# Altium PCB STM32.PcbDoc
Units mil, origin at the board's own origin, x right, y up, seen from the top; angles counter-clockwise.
Board outline 4734.45 x 4734.65 mil, 2 copper layers (Top Layer, Bottom Layer); 1 components, 161 nets, 42 pads, 0 vias.
Unrouted connection lines stored in the file: 460.
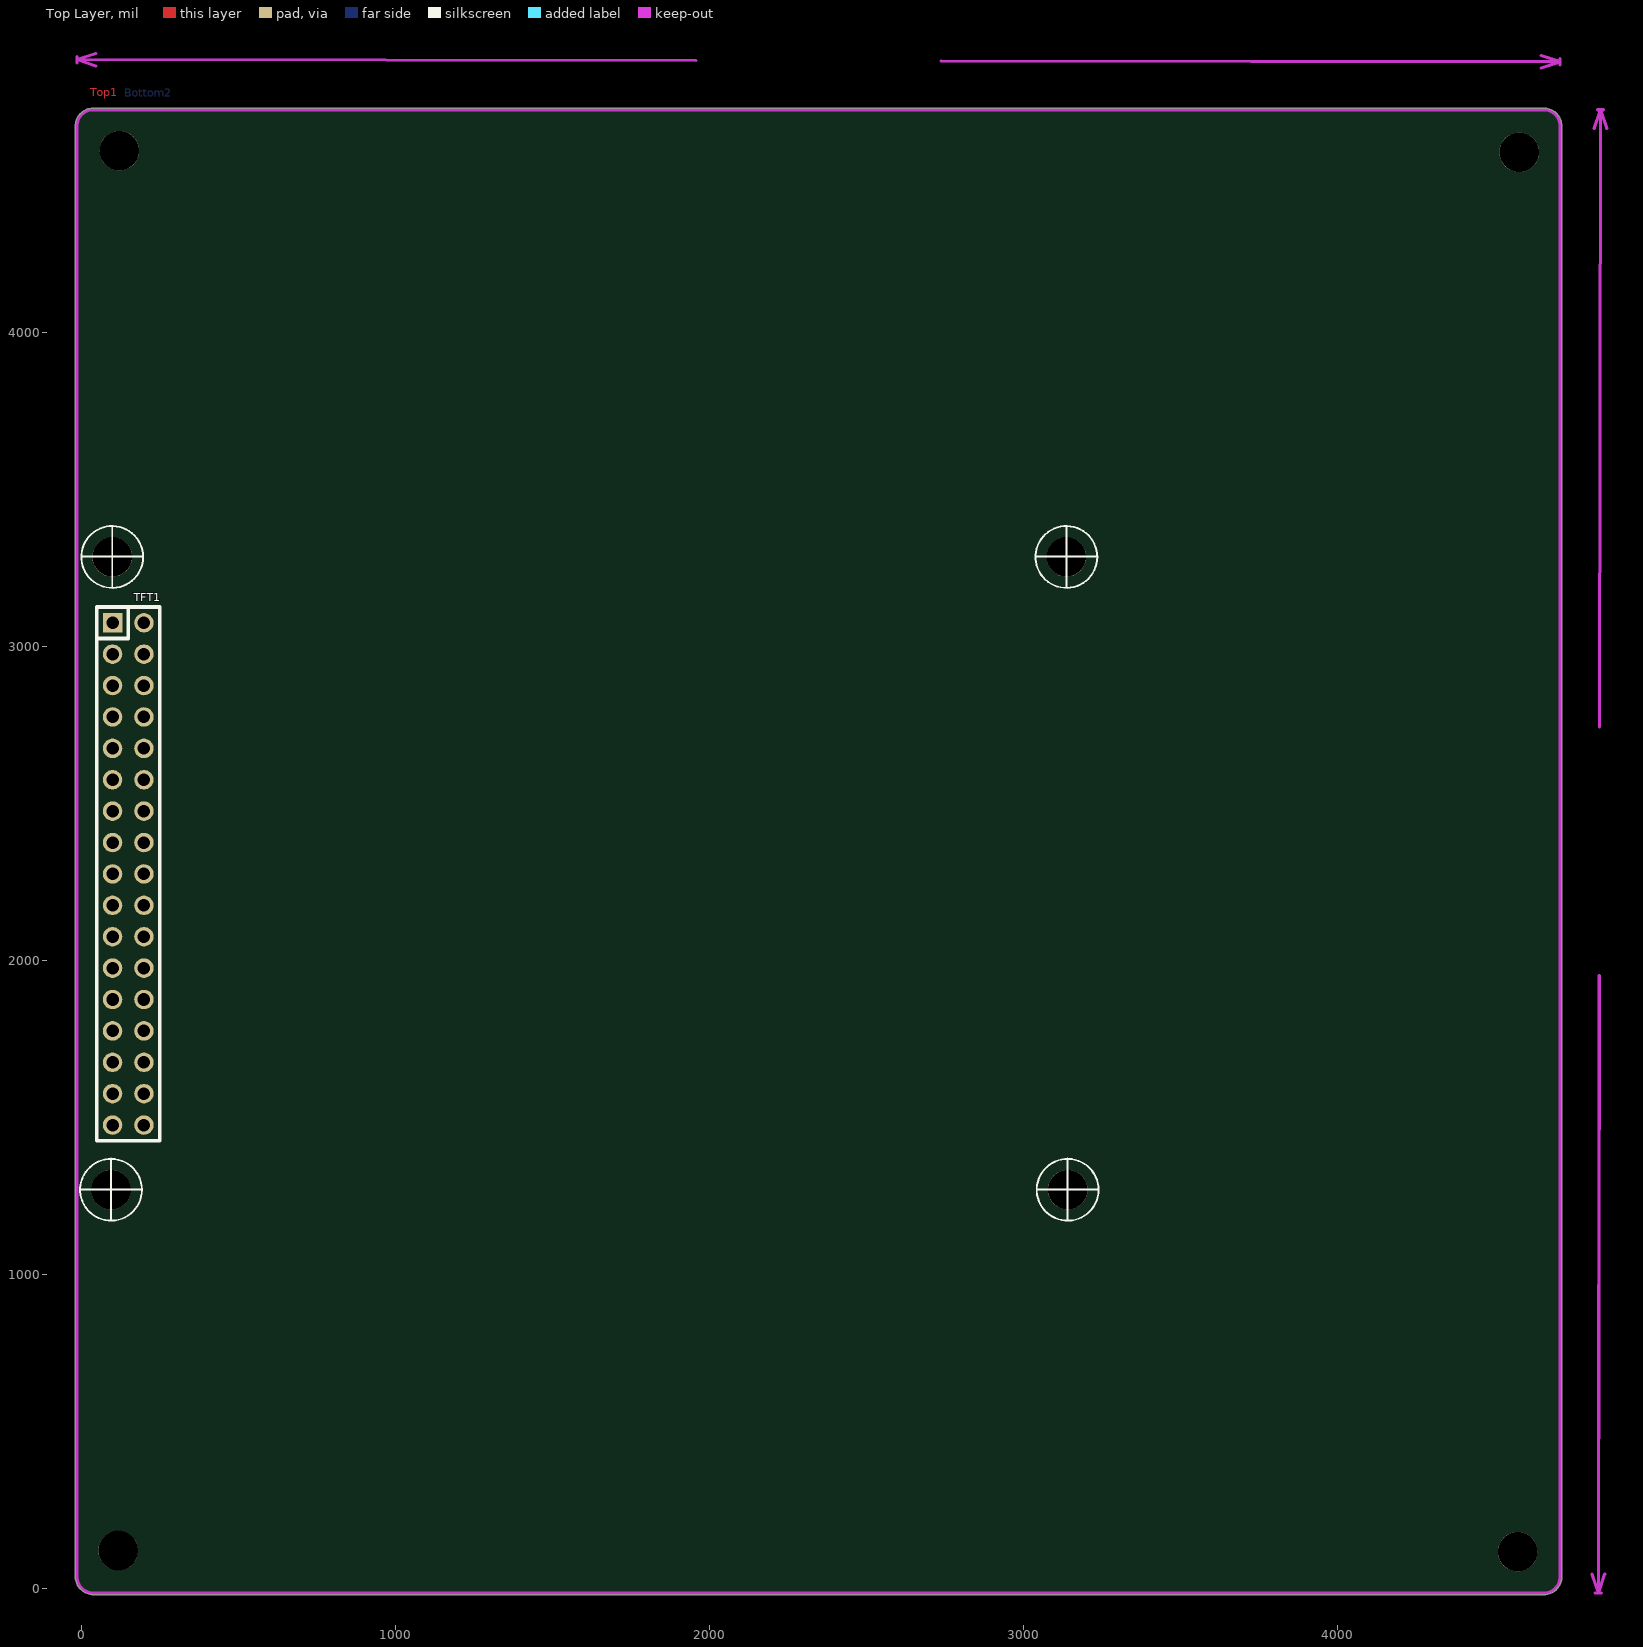
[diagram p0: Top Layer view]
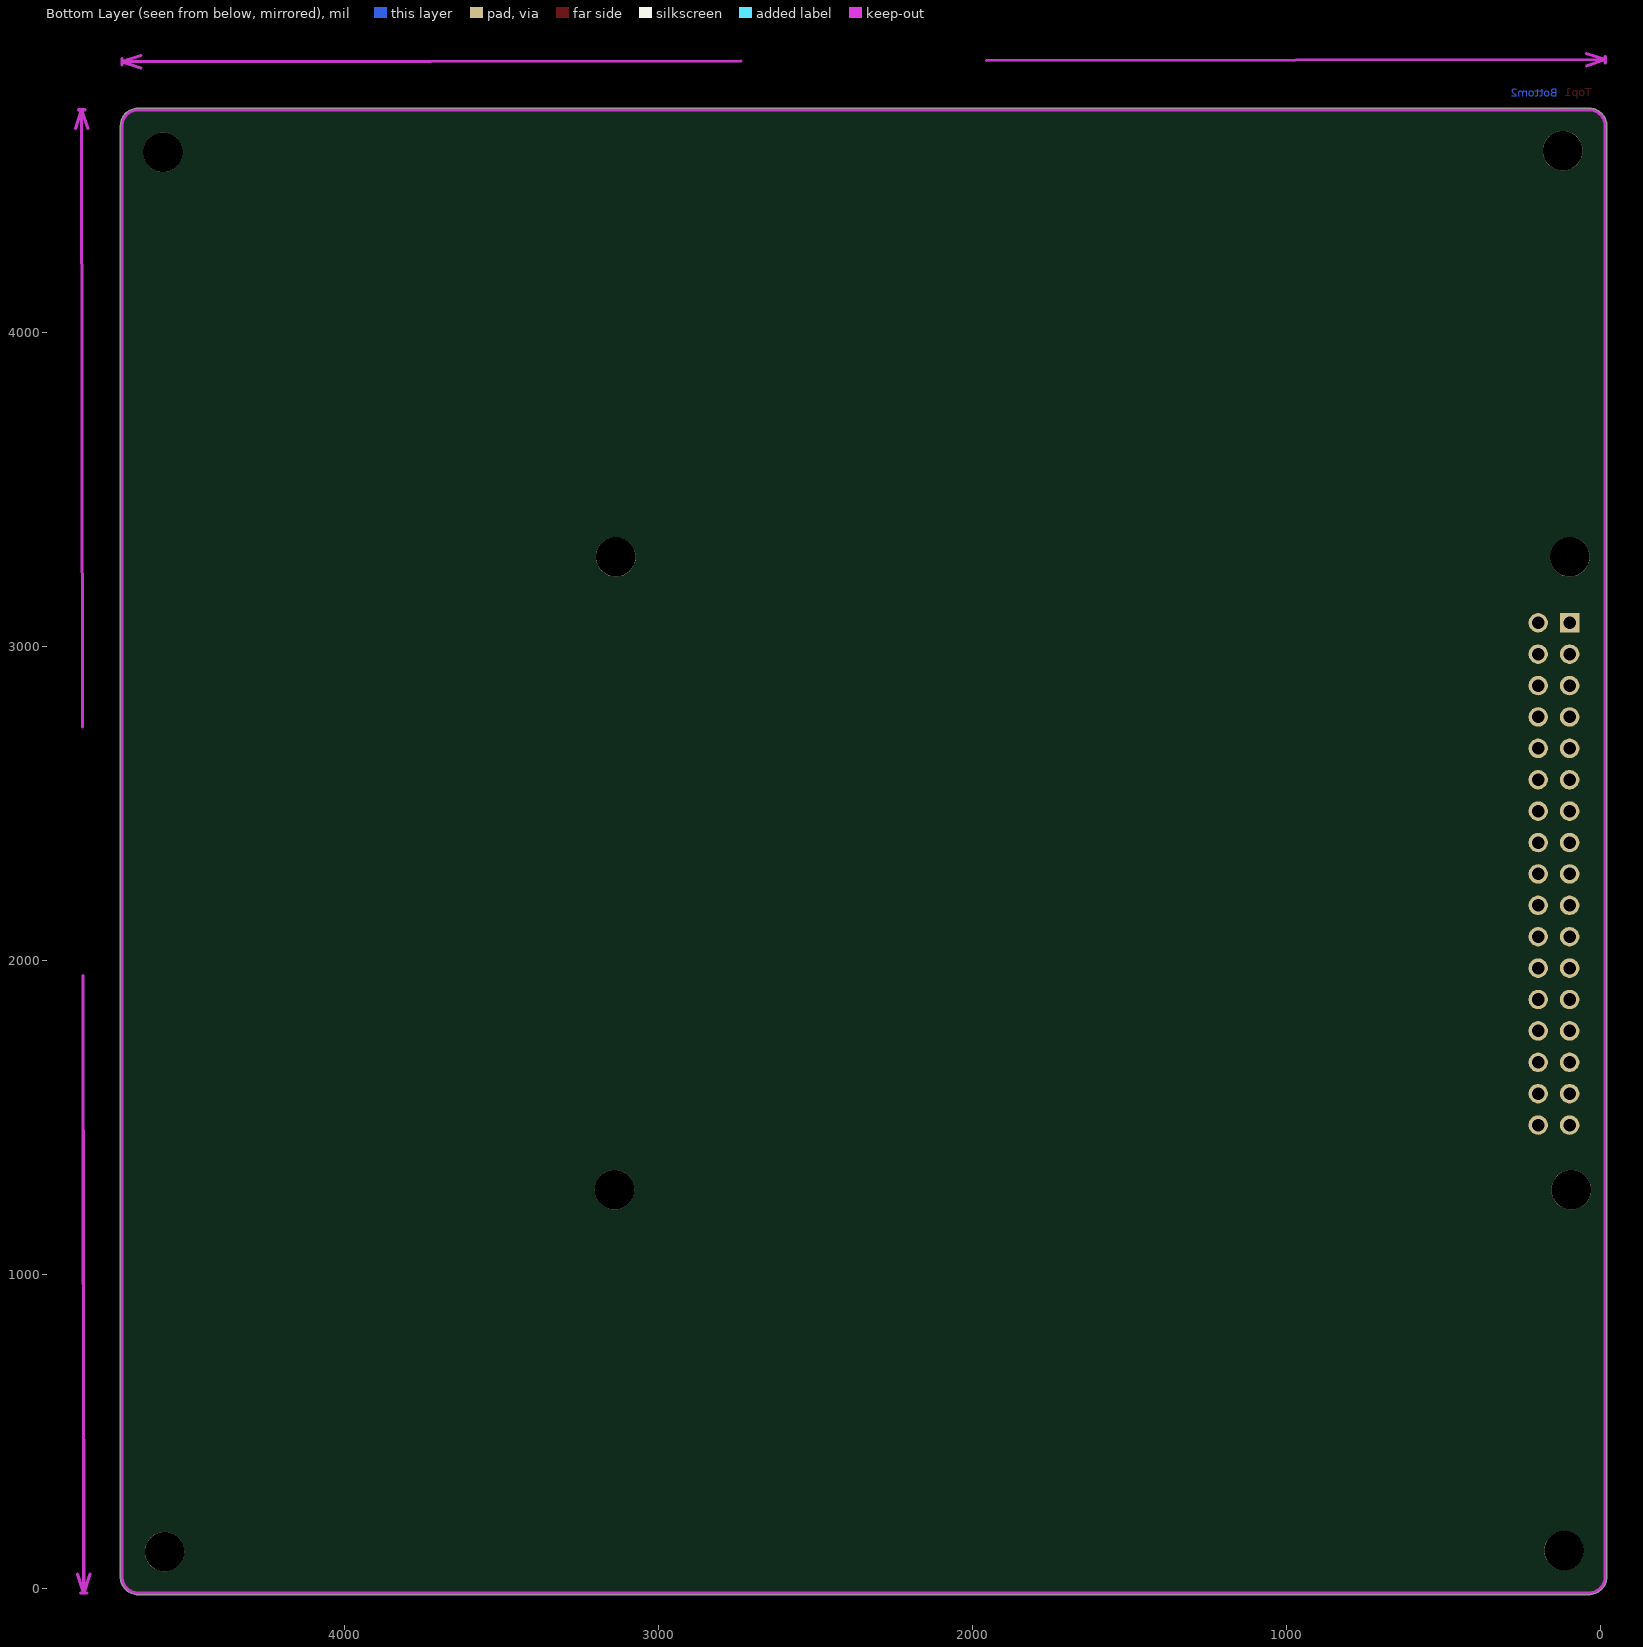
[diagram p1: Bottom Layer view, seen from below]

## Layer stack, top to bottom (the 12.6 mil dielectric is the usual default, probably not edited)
Top Layer: signal copper 1.4
Dielectric: dielectric 12.6, FR-4, Dk 4.8
Bottom Layer: signal copper 1.4

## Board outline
-20.01,40.16 ccw(c36.65,36.65) 31.59,-19.9 ccw(c33.62,-15.31) 33.62,-20.32 4654.15,-20.32 ccw(c4657.65,36.35) 4714.31,32.68 ccw(c4709.31,33) 4714.32,33 4714.32,4654.15 ccw(c4657.65,4657.65) 4714.43,4657.65 ccw(c4657.65,4657.65) 4661.32,4714.31 ccw(c4661,4709.31) 4661,4714.32 40.16,4714.32 ccw(c36.65,4657.65) -20,4661.32 ccw(c-15,4661) -20.01,4661

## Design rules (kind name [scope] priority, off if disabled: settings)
Clearance [All] p1: gap=7
ComponentClearance [All] p1: gap=0 collisioncheckmode=3 verticalgap=0 showdistances=FALSE
HoleSize [All] p1: absolutevalues=TRUE maxlimit=200 minlimit=1 maxpercent=80.000 minpercent=20.000
HoleToHoleClearance [All] p1: gap=0 allowstackedmicrovias=TRUE
MinimumSolderMaskSliver [All] p1: minsoldermaskwidth=0
PolygonConnect [All] p1: connectstyle=Relief reliefconductorwidth=10 reliefentries=4 polygonreliefangle="90 Angle"
RoutingVias [All] p1: holewidth=28 width=50 viastyle="Through Hole" minholewidth=28 minwidth=50 maxholewidth=28 maxwidth=50
SilkToSilkClearance [All] p1: silktosilkclearance=0
SilkscreenOverComponentPads [All] p1: minsilkscreentomaskgap=0
SolderMaskExpansion [All] p1: expansion=4
Width [All] p1: maxlimit=10 minlimit=10 preferedwidth=10
22 further rules are at their usual default settings.

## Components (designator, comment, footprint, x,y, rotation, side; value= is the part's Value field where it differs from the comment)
TFT1 "TFT_LCD" LCD240320 1617,2277 r180 top locked

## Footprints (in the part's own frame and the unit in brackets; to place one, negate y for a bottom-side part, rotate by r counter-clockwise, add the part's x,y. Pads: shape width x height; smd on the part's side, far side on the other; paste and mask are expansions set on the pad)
LCD240320 [mil]
  round 125.98 hole 125.98 unplated: 0(-1523.62,1007.87) 0(-1519.69,-1007.87) 0(1519.69,-1007.87) 0(1523.62,1007.87)
  rect 62x62 hole 40: 1(1518.66,-798.27)
  round 62 hole 40: 2(1418.66,-798.27) 3(1518.66,-698.27) 4(1418.66,-698.27) 5(1518.66,-598.27) 6(1418.66,-598.27) 7(1518.66,-498.27) 8(1418.66,-498.27) 9(1518.66,-398.27) 10(1418.66,-398.27) 11(1518.66,-298.27) 12(1418.66,-298.27) 13(1518.66,-198.27) 14(1418.66,-198.27) 15(1518.66,-98.27) 16(1418.66,-98.27) 17(1518.66,1.73) 18(1418.66,1.73) 19(1518.66,101.73) 20(1418.66,101.73) 21(1518.66,201.73) 22(1418.66,201.73) 23(1518.66,301.73) 24(1418.66,301.73) 25(1518.66,401.73) 26(1418.66,401.73) 27(1518.66,501.73) 28(1418.66,501.73) 29(1518.66,601.73) 30(1418.66,601.73) 31(1518.66,701.73) 32(1418.66,701.73) 33(1518.66,801.73) 34(1418.66,801.73)
  silkscreen extent -1622,-1107 1622,1106

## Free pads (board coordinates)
  round 125.98 hole 125.98 unplated: ""(116.11,120.11) ""(120.11,4578.89) ""(4573.89,116.11) ""(4578.89,4573.89)

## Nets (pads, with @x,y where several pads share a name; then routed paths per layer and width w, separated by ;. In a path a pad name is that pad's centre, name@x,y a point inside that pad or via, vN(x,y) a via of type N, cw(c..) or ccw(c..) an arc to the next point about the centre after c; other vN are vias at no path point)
2V5: 
2V8: 
3V3: TFT1.24 TFT1.25
5V: TFT1.28
5V-IN: 
AGND: 
BOOT0: 
BOOT1: 
FM_ANT: 
FM_L: 
FM_R: 
GND: TFT1.22 TFT1.26 TFT1.27
LEDA: 
LEDB: 
LEFT: 
MICN: 
MICP: 
NetC4_2: 
NetC5_1: 
NetC14_1: 
NetC14_2: 
NetC15_2: 
NetC16_1: 
NetC16_2: 
NetC17_1: 
NetC25_1: 
NetC26_1: 
NetC27_1: 
NetC33_1: 
NetC34_1: 
NetC35_1: 
NetC36_1: 
NetC37_1: 
NetC37_2: 
NetC38_2: 
NetC39_1: 
NetC40_2: 
NetC42_2: 
NetC48_1: 
NetC48_2: 
NetC59_1: 
NetC59_2: 
NetD1_1: 
NetD2_1: 
NetD3_1: 
NetD4_1: 
NetD5_1: 
NetD6_1: 
NetJ3_2: 
NetJ6_1: 
NetJ6_2: 
NetJ7_1: 
NetJ7_2: 
NetQ1_2: 
NetQ1_3: 
NetQ2_2: 
NetQ2_3: 
NetR3_2: 
NetR4_2: 
NetR18_2: 
NetR19_2: 
NetR20_2: 
NetR21_2: 
NetR43_1: 
NetR47_2: 
NetR48_2: 
OSC_I: 
OSC_O: 
PA0: 
PA1: 
PA2: 
PA3: 
PA4: 
PA5: TFT1.34
PA6: TFT1.29
PA7: TFT1.30
PA9: 
PA10: 
PA11: 
PA12: 
PA13: 
PA14: 
PA15: 
PB0: 
PB1: 
PB2: 
PB3: 
PB4: 
PB5: 
PB6: 
PB7: 
PB8: 
PB9: 
PB10: 
PB11: 
PB12: TFT1.31
PB13: TFT1.23
PB14: 
PB15: 
PC0: 
PC1: 
PC2: 
PC3: TFT1.33
PC4: 
PC5: 
PC6: 
PC7: 
PC8: 
PC9: 
PC10: 
PC11: 
PC12: 
PC13: 
PC14: 
PC15: 
PD0: 
PD1: 
PD2: 
PD3: 
PD4: 
PD5: 
PD6: 
PD7: 
PD8: 
PD9: 
PD10: 
PD11: 
PD12: TFT1.1
PD13: TFT1.2
PD14: TFT1.3
PD15: TFT1.4
PE0: TFT1.6
PE1: TFT1.7
PE2: TFT1.8
PE3: TFT1.9
PE4: TFT1.10
PE5: TFT1.11
PE6: TFT1.12
PE7: TFT1.13
PE8: TFT1.14
PE9: TFT1.15
PE10: TFT1.16
PE11: TFT1.17
PE12: TFT1.18
PE13: TFT1.19
PE14: TFT1.20
PE15: TFT1.21
RESET: TFT1.5
RIGHT: 
RXD1: 
RXD2: 
TPIN+: 
TPIN-: 
TPOUT+: 
TPOUT-: 
TXD1: 
TXD2: 
U5V: 
VBAT: 
VS_LEFT: 
VS_RIGHT: 
pads on no net: TFT1.0 TFT1.32

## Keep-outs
Keep-Out Layer:
  lines w10: -15.01,4859 -14.99,4879 ; 33.31,-15 cw(c36.65,36.65) -15,40 -15,4661 cw(c36.65,4657.65) 40,4709.31 ; 33.62,-15.31 4654.31,-15.31 ccw(c4657.65,36.35) 4709.31,33 4709.31,4654.31 ccw(c4657.65,4657.65) 4661,4709.31 37.31,4709.31 ; 44.97,4848.92 -15,4869 ; 45.03,4888.92 -15,4869 ; 1956.28,4866.21 -15,4869 ; 2738.03,4865.1 4709.31,4862.31 ; 4649.28,4842.39 4709.31,4862.31 ; 4649.34,4882.39 4709.31,4862.31 ; 4709.29,4852.31 4709.32,4872.31 ; 4811.39,44.72 4831.31,-15.31 ; 4817.92,4649.34 4838,4709.31 ; 4821.31,-15.29 4841.31,-15.32 ; 4828,4709.32 4848,4709.29 ; 4834.09,1951.12 4831.31,-15.31 ; 4835.21,2742.88 4838,4709.31 ; 4851.39,44.66 4831.31,-15.31 ; 4857.92,4649.28 4838,4709.31
  text "4724.313 (mil)" at 1966.22,4830.2 h25 r359.92
  text "4724.622 (mil)" at 4870.1,1961.07 h25 r89.92

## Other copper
Top Layer:
  text "Top1" at 28,4752 h25
Bottom Layer:
  text "Bottom2" at 136,4751 h25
